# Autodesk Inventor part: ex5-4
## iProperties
Shininess: 64.0
Length Units: 11269
Angle Units: 11279
Time Units: 11290
Mass Units: 11283
Length Display Precision: 3
Angle Display Precision: 2
Compacted: True
Part Number: ex5-4
Document SubType Name: Modeling
Created: 2003-11
Cost Center: 0 kg
Designer: Elise Moss
Authority: 11426.17 mm^3
Manufacturer: Standard
Standards Organization: Custom
Density: 0.0
Volumn: 0.0
Area: 0.0
PropertySet Name: Model Information
Control State: 0
Master: False
Checked Out: False
SaveDate: 2003-11-14
SaveTime: 19:35
TotalMass: 0 kg
TotalVolume: 11426.17 mm^3
Author: Elise Moss
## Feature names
1. Extrusion1
2. Hole1
3. Shell3
